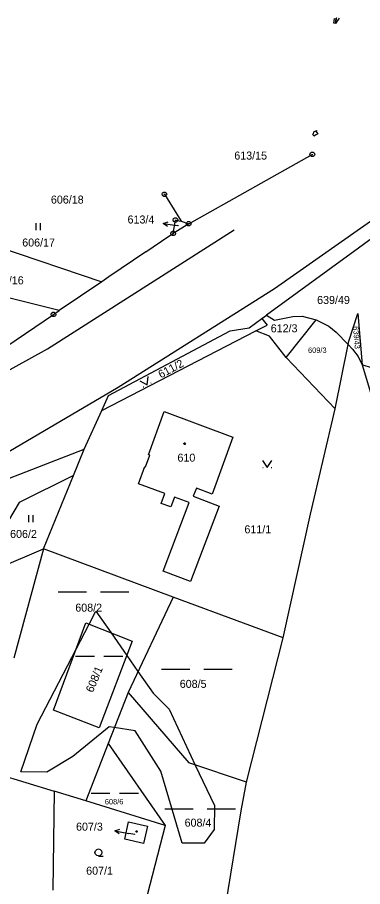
# Model space of a CAD drawing. Extents: x -759699 to -757730, y -1172308 to -1170857.
# Drawn here: x -758932.7 to -758859.4, y -1171642.4 to -1171457.7 of the extents above; entities that cross this region are included whole.
import ezdxf

# ---------------------------------------------------------------- set-up
doc = ezdxf.new("R2010")
doc.units = 0
for name, color, linetype in [('Vrstva 1', 7, 'Continuous'), ('Vrstva 11', 7, 'Continuous'), ('Vrstva 12', 7, 'Continuous'), ('Vrstva 13', 7, 'Continuous'), ('Vrstva 2', 7, 'Continuous'), ('Vrstva 3', 7, 'Continuous'), ('Vrstva 4', 7, 'Continuous'), ('Vrstva 5', 7, 'Continuous'), ('Vrstva 7', 7, 'Continuous'), ('Vrstva 8', 7, 'Continuous')]:
    doc.layers.add(name, color=color, linetype=linetype)

msp = doc.modelspace()

# ---------------------------------------------------------------- linework, layer by layer
at = {"layer": 'Vrstva 1'}
for p, q in [((-758896.35, -1171501.57), (-758870.1, -1171486.83)), ((-758870.1, -1171486.83), (-758870.1, -1171486.83)), ((-758870.1, -1171486.83), (-758870.1, -1171486.83)), ((-758901.51, -1171495.3), (-758901.51, -1171495.3)), ((-758901.51, -1171495.3), (-758898.88, -1171499.53)), ((-758901.51, -1171495.3), (-758901.51, -1171495.3)), ((-758899.66, -1171503.62), (-758899.17, -1171500.77)), ((-758899.17, -1171500.77), (-758897.96, -1171501.02)), ((-758898.88, -1171499.53), (-758897.96, -1171501.02)), ((-758896.35, -1171501.57), (-758899.66, -1171503.62)), ((-758897.96, -1171501.02), (-758896.35, -1171501.57)), ((-758896.35, -1171501.57), (-758896.35, -1171501.57)), ((-758946.27, -1171503.31), (-758914.82, -1171513.88)), ((-758905.46, -1171507.54), (-758900.57, -1171504.23)), ((-758900.57, -1171504.23), (-758899.66, -1171503.62)), ((-758856.32, -1171503.88), (-758860.31, -1171506.78)), ((-758905.46, -1171507.54), (-758913.32, -1171512.87)), ((-758905.46, -1171507.54), (-758905.46, -1171507.54)), ((-758860.31, -1171506.78), (-758879.83, -1171520.98)), ((-758923.84, -1171519.99), (-758949.6, -1171513.62)), ((-758914.82, -1171513.88), (-758923.84, -1171519.99)), ((-758913.32, -1171512.87), (-758914.82, -1171513.88)), ((-758949.81, -1171537.59), (-758925.08, -1171520.83)), ((-758925.08, -1171520.83), (-758923.84, -1171519.99)), ((-758880.8, -1171521.68), (-758879.83, -1171520.98)), ((-758879.83, -1171520.98), (-758878.12, -1171522.07)), ((-758878.12, -1171522.07), (-758874.21, -1171521.27)), ((-758874.21, -1171521.27), (-758872.25, -1171521.22)), ((-758872.25, -1171521.22), (-758869.27, -1171521.97)), ((-758862.34, -1171526.52), (-758860.47, -1171520.62)), ((-758860.47, -1171520.62), (-758859.54, -1171531.55)), ((-758883.49, -1171523.64), (-758880.8, -1171521.68)), ((-758882.07, -1171524.31), (-758879.66, -1171523.07)), ((-758880.8, -1171521.68), (-758879.66, -1171523.07)), ((-758875.67, -1171529.97), (-758869.27, -1171521.97)), ((-758869.27, -1171521.97), (-758866.62, -1171523.29)), ((-758914.83, -1171541.22), (-758882.07, -1171524.31)), ((-758913.4, -1171538.04), (-758887.56, -1171524.31)), ((-758887.56, -1171524.31), (-758883.49, -1171523.64)), ((-758879.19, -1171525.47), (-758882.07, -1171524.31)), ((-758866.62, -1171523.29), (-758865.04, -1171524.57)), ((-758865.04, -1171524.57), (-758862.49, -1171527.23)), ((-758875.67, -1171529.97), (-758879.19, -1171525.47)), ((-758862.49, -1171527.23), (-758862.34, -1171526.52)), ((-758865.27, -1171540.84), (-758862.49, -1171527.23)), ((-758862.49, -1171527.23), (-758861.55, -1171528.21)), ((-758861.55, -1171528.21), (-758860.37, -1171529.76)), ((-758865.27, -1171540.84), (-758875.67, -1171529.97)), ((-758860.37, -1171529.76), (-758859.54, -1171531.55)), ((-758859.54, -1171531.55), (-758853.32, -1171552.22)), ((-758854.03, -1171533.3), (-758859.54, -1171531.55)), ((-758914.83, -1171541.22), (-758913.4, -1171538.04)), ((-758918.53, -1171549.43), (-758914.83, -1171541.22)), ((-758904.87, -1171550.65), (-758901.54, -1171541.46)), ((-758901.54, -1171541.46), (-758886.98, -1171546.87)), ((-758870.46, -1171563.25), (-758865.27, -1171540.84)), ((-758886.98, -1171546.87), (-758891.37, -1171559.02)), ((-758937.1, -1171556.66), (-758918.53, -1171549.43)), ((-758920.82, -1171555.04), (-758918.53, -1171549.43)), ((-758905.54, -1171553.17), (-758904.64, -1171550.73)), ((-758904.64, -1171550.73), (-758904.87, -1171550.65)), ((-758907.01, -1171556.78), (-758905.69, -1171553.12)), ((-758905.69, -1171553.12), (-758905.54, -1171553.17)), ((-758920.82, -1171555.04), (-758932.37, -1171560.76)), ((-758927.21, -1171570.62), (-758920.82, -1171555.04)), ((-758901.41, -1171558.87), (-758907.01, -1171556.78)), ((-758894.72, -1171557.69), (-758895.4, -1171559.39)), ((-758891.37, -1171559.02), (-758894.72, -1171557.69)), ((-758902.17, -1171560.96), (-758901.41, -1171558.87)), ((-758899.36, -1171559.63), (-758900.14, -1171561.69)), ((-758896.27, -1171560.8), (-758899.36, -1171559.63)), ((-758895.4, -1171559.39), (-758889.92, -1171561.57)), ((-758932.37, -1171560.76), (-758942.1, -1171576.91)), ((-758900.14, -1171561.69), (-758902.17, -1171560.96)), ((-758901.8, -1171575.38), (-758896.27, -1171560.8)), ((-758889.92, -1171561.57), (-758895.98, -1171577.55)), ((-758876.28, -1171589.53), (-758870.46, -1171563.25)), ((-758942.1, -1171576.91), (-758927.21, -1171570.62)), ((-758927.21, -1171570.62), (-758933.5, -1171593.84)), ((-758899.67, -1171580.85), (-758927.21, -1171570.62)), ((-758895.98, -1171577.55), (-758901.8, -1171575.38)), ((-758899.67, -1171580.85), (-758909.22, -1171601.09)), ((-758876.28, -1171589.53), (-758899.67, -1171580.85)), ((-758925.06, -1171604.87), (-758918.21, -1171586.34)), ((-758918.21, -1171586.34), (-758908.34, -1171590.22)), ((-758884.11, -1171620.15), (-758876.28, -1171589.53)), ((-758908.34, -1171590.22), (-758915.4, -1171608.61)), ((-758909.22, -1171601.09), (-758913.47, -1171611.98)), ((-758909.22, -1171601.09), (-758896.34, -1171616.06)), ((-758915.4, -1171608.61), (-758925.06, -1171604.87)), ((-758913.47, -1171611.98), (-758918.23, -1171624.15)), ((-758913.47, -1171611.98), (-758901.34, -1171629.35)), ((-758884.11, -1171620.15), (-758896.34, -1171616.06)), ((-758939.9, -1171617.5), (-758924.94, -1171622.09)), ((-758885.19, -1171626.24), (-758884.11, -1171620.15)), ((-758924.94, -1171622.09), (-758925.22, -1171643.14)), ((-758918.23, -1171624.15), (-758924.94, -1171622.09)), ((-758901.34, -1171629.35), (-758918.23, -1171624.15)), ((-758889.72, -1171653.54), (-758885.19, -1171626.24)), ((-758909.9, -1171632.3), (-758909.14, -1171628.6)), ((-758909.14, -1171628.6), (-758905.11, -1171629.52)), ((-758905.11, -1171629.52), (-758905.95, -1171633.19)), ((-758901.34, -1171629.35), (-758905.21, -1171644.2)), ((-758905.95, -1171633.19), (-758909.9, -1171632.3))]:
    msp.add_line(p, q, dxfattribs=at)
at = {"layer": 'Vrstva 11'}
for p, q in [((-758917.52, -1171586.61), (-758916.08, -1171583.82)), ((-758916.08, -1171583.82), (-758912.85, -1171588.45)), ((-758920.27, -1171591.91), (-758917.52, -1171586.61)), ((-758912.85, -1171588.45), (-758909.5, -1171593.25)), ((-758928.54, -1171607.86), (-758920.27, -1171591.91)), ((-758909.5, -1171593.25), (-758907.13, -1171596.65)), ((-758907.13, -1171596.65), (-758903.89, -1171601.29)), ((-758903.89, -1171601.29), (-758900.52, -1171604.7)), ((-758900.52, -1171604.7), (-758894.95, -1171616.53)), ((-758932, -1171618), (-758928.54, -1171607.86)), ((-758913.27, -1171608.41), (-758920.95, -1171614.7)), ((-758912.15, -1171608.59), (-758913.27, -1171608.41)), ((-758907.76, -1171609.3), (-758912.15, -1171608.59)), ((-758902.3, -1171617.82), (-758907.76, -1171609.3)), ((-758920.95, -1171614.7), (-758926.48, -1171618.04)), ((-758894.95, -1171616.53), (-758890.9, -1171625.11)), ((-758926.48, -1171618.04), (-758932, -1171618)), ((-758897.74, -1171633.1), (-758902.3, -1171617.82)), ((-758890.9, -1171625.11), (-758890.93, -1171630.19)), ((-758890.93, -1171630.19), (-758893.07, -1171633.14)), ((-758893.07, -1171633.14), (-758897.74, -1171633.1))]:
    msp.add_line(p, q, dxfattribs=at)
at = {"layer": 'Vrstva 12'}
for p, q in [((-758904.87, -1171550.65), (-758901.54, -1171541.46)), ((-758901.54, -1171541.46), (-758886.98, -1171546.87)), ((-758886.98, -1171546.87), (-758891.37, -1171559.02)), ((-758905.54, -1171553.17), (-758904.64, -1171550.73)), ((-758904.64, -1171550.73), (-758904.87, -1171550.65)), ((-758907.01, -1171556.78), (-758905.69, -1171553.12)), ((-758905.69, -1171553.12), (-758905.54, -1171553.17)), ((-758901.41, -1171558.87), (-758907.01, -1171556.78)), ((-758894.72, -1171557.69), (-758895.4, -1171559.39)), ((-758891.37, -1171559.02), (-758894.72, -1171557.69)), ((-758902.17, -1171560.96), (-758901.41, -1171558.87)), ((-758899.36, -1171559.63), (-758900.14, -1171561.69)), ((-758896.27, -1171560.8), (-758899.36, -1171559.63)), ((-758895.4, -1171559.39), (-758889.92, -1171561.57)), ((-758900.14, -1171561.69), (-758902.17, -1171560.96)), ((-758901.8, -1171575.38), (-758896.27, -1171560.8)), ((-758889.92, -1171561.57), (-758895.98, -1171577.55)), ((-758895.98, -1171577.55), (-758901.8, -1171575.38)), ((-758909.9, -1171632.3), (-758909.14, -1171628.6)), ((-758909.14, -1171628.6), (-758905.11, -1171629.52)), ((-758905.11, -1171629.52), (-758905.95, -1171633.19)), ((-758905.95, -1171633.19), (-758909.9, -1171632.3))]:
    msp.add_line(p, q, dxfattribs=at)
at = {"layer": 'Vrstva 13'}
for p, q in [((-758865.55, -1171458.98), (-758865.41, -1171457.99)), ((-758865.41, -1171457.99), (-758865.01, -1171458.05)), ((-758864.39, -1171457.87), (-758865.16, -1171459.04)), ((-758865.01, -1171458.05), (-758865.16, -1171459.04)), ((-758865.16, -1171459.04), (-758865.01, -1171458.05)), ((-758865.01, -1171458.05), (-758864.88, -1171457.73)), ((-758864.88, -1171457.73), (-758864.88, -1171457.73)), ((-758864.39, -1171457.87), (-758864.39, -1171457.87)), ((-758865.16, -1171459.04), (-758865.55, -1171458.98)), ((-758870.02, -1171482.52), (-758869.86, -1171482.43)), ((-758869.78, -1171482.96), (-758870.02, -1171482.52)), ((-758869.86, -1171482.43), (-758869.78, -1171482.06)), ((-758869.78, -1171482.06), (-758869.21, -1171481.74)), ((-758868.9, -1171482.48), (-758869.78, -1171482.96)), ((-758869.21, -1171481.74), (-758869.3, -1171482.13)), ((-758869.3, -1171482.13), (-758869.14, -1171482.04)), ((-758869.14, -1171482.04), (-758868.9, -1171482.48))]:
    msp.add_line(p, q, dxfattribs=at)
at = {"layer": 'Vrstva 3'}
for p, q in [((-758928.85, -1171501.43), (-758928.85, -1171502.93)), ((-758927.85, -1171502.93), (-758927.85, -1171501.43)), ((-758904.404, -1171535.412), (-758904.315, -1171535.366)), ((-758906.005, -1171536.234), (-758905.916, -1171536.188)), ((-758880.62, -1171553.37), (-758880.52, -1171553.37)), ((-758878.82, -1171553.37), (-758878.72, -1171553.37)), ((-758930.4, -1171563.43), (-758930.4, -1171564.93)), ((-758929.4, -1171564.93), (-758929.4, -1171563.43)), ((-758924.09, -1171579.75), (-758918.09, -1171579.75)), ((-758915.09, -1171579.75), (-758909.09, -1171579.75)), ((-758920.385, -1171593.43), (-758916.365, -1171593.43)), ((-758914.355, -1171593.43), (-758910.335, -1171593.43)), ((-758902.14, -1171596.2), (-758896.14, -1171596.2)), ((-758893.14, -1171596.2), (-758887.14, -1171596.2)), ((-758917.095, -1171622.54), (-758913.075, -1171622.54)), ((-758911.065, -1171622.54), (-758907.045, -1171622.54)), ((-758901.43, -1171625.83), (-758895.43, -1171625.83)), ((-758892.43, -1171625.83), (-758886.43, -1171625.83))]:
    msp.add_line(p, q, dxfattribs=at)
for points in [[(-758906.734, -1171534.922), (-758905.16, -1171535.8), (-758904.955, -1171534.009)], [(-758880.67, -1171551.87), (-758879.67, -1171553.37), (-758878.67, -1171551.87)], [(-758915.52, -1171635.84), (-758915.9, -1171635.74), (-758916.17, -1171635.47), (-758916.27, -1171635.1), (-758916.17, -1171634.73), (-758915.9, -1171634.46), (-758915.53, -1171634.36), (-758915.16, -1171634.46), (-758914.89, -1171634.73), (-758914.79, -1171635.11), (-758914.89, -1171635.49), (-758915.16, -1171635.76), (-758915.54, -1171635.86), (-758914.54, -1171635.86)]]:
    msp.add_lwpolyline(points, dxfattribs=at)
at = {"layer": 'Vrstva 4'}
for p, q in [((-758878.1, -1171515.3), (-758834.46, -1171484.59)), ((-758926.31, -1171528.12), (-758886.7, -1171502.88)), ((-758886.7, -1171502.88), (-758886.7, -1171502.88)), ((-758911.34, -1171536.26), (-758878.1, -1171515.3)), ((-758948.39, -1171540.22), (-758926.31, -1171528.12)), ((-758940.14, -1171553.19), (-758911.34, -1171536.26))]:
    msp.add_line(p, q, dxfattribs=at)
at = {"layer": 'Vrstva 5'}
for points in [[(-758897.15, -1171548.12), (-758897.06, -1171548.27), (-758897.15, -1171548.42), (-758897.33, -1171548.42), (-758897.42, -1171548.27), (-758897.33, -1171548.12)], [(-758907.34, -1171630.49), (-758907.25, -1171630.64), (-758907.34, -1171630.79), (-758907.52, -1171630.79), (-758907.61, -1171630.64), (-758907.52, -1171630.49)]]:
    msp.add_lwpolyline(points, close=True, dxfattribs=at)
at = {"layer": 'Vrstva 7'}
for p, q in [((-758901.759, -1171501.507), (-758898.79, -1171501.94)), ((-758898.53, -1171501.98), (-758898.79, -1171501.94)), ((-758912.034, -1171630.472), (-758909.09, -1171631.05)), ((-758907.81, -1171631.3), (-758909.09, -1171631.05))]:
    msp.add_line(p, q, dxfattribs=at)
for points in [[(-758900.841, -1171502.146), (-758901.759, -1171501.507), (-758900.697, -1171501.157)], [(-758911.149, -1171631.155), (-758912.034, -1171630.472), (-758910.956, -1171630.174)]]:
    msp.add_lwpolyline(points, dxfattribs=at)
at = {"layer": 'Vrstva 8'}
for p, q in [((-758870.22, -1171486.83), (-758869.98, -1171486.83)), ((-758901.63, -1171495.3), (-758901.39, -1171495.3)), ((-758899.29, -1171500.77), (-758899.05, -1171500.77)), ((-758896.47, -1171501.57), (-758896.23, -1171501.57)), ((-758899.78, -1171503.62), (-758899.54, -1171503.62)), ((-758925.2, -1171520.83), (-758924.96, -1171520.83))]:
    msp.add_line(p, q, dxfattribs=at)
for points in [[(-758869.95, -1171486.35), (-758869.7, -1171486.53), (-758869.6, -1171486.82), (-758869.7, -1171487.11), (-758869.95, -1171487.29), (-758870.26, -1171487.29), (-758870.51, -1171487.11), (-758870.61, -1171486.82), (-758870.51, -1171486.53), (-758870.26, -1171486.35)], [(-758901.36, -1171494.82), (-758901.11, -1171495), (-758901.01, -1171495.29), (-758901.11, -1171495.58), (-758901.36, -1171495.76), (-758901.67, -1171495.76), (-758901.92, -1171495.58), (-758902.02, -1171495.29), (-758901.92, -1171495), (-758901.67, -1171494.82)], [(-758899.02, -1171500.29), (-758898.77, -1171500.47), (-758898.67, -1171500.76), (-758898.77, -1171501.05), (-758899.02, -1171501.23), (-758899.33, -1171501.23), (-758899.58, -1171501.05), (-758899.68, -1171500.76), (-758899.58, -1171500.47), (-758899.33, -1171500.29)], [(-758896.2, -1171501.09), (-758895.95, -1171501.27), (-758895.85, -1171501.56), (-758895.95, -1171501.85), (-758896.2, -1171502.03), (-758896.51, -1171502.03), (-758896.76, -1171501.85), (-758896.86, -1171501.56), (-758896.76, -1171501.27), (-758896.51, -1171501.09)], [(-758899.51, -1171503.14), (-758899.26, -1171503.32), (-758899.16, -1171503.61), (-758899.26, -1171503.9), (-758899.51, -1171504.08), (-758899.82, -1171504.08), (-758900.07, -1171503.9), (-758900.17, -1171503.61), (-758900.07, -1171503.32), (-758899.82, -1171503.14)], [(-758924.93, -1171520.35), (-758924.68, -1171520.53), (-758924.58, -1171520.82), (-758924.68, -1171521.11), (-758924.93, -1171521.29), (-758925.24, -1171521.29), (-758925.49, -1171521.11), (-758925.59, -1171520.82), (-758925.49, -1171520.53), (-758925.24, -1171520.35)]]:
    msp.add_lwpolyline(points, close=True, dxfattribs=at)

# ---------------------------------------------------------------- texts
at = {"layer": 'Vrstva 2'}
for s, height, p in [('613/15', 1.7, (-758886.67, -1171487.93)), ('606/18', 1.7, (-758925.621, -1171497.28)), ('613/4', 0.1, (-758898.717, -1171501.98)), ('606/17', 1.7, (-758931.711, -1171506.4)), ('606/16', 1.7, (-758938.351, -1171514.43)), ('639/49', 1.7, (-758869.079, -1171518.6)), ('612/3', 1.7, (-758878.936, -1171524.62)), ('609/3', 1.14, (-758871.009, -1171528.99)), ('610', 1.7, (-758898.743, -1171552.1)), ('611/1', 1.7, (-758884.519, -1171567.32)), ('606/2', 1.7, (-758934.284, -1171568.3)), ('608/2', 1.7, (-758920.44, -1171583.95)), ('608/5', 1.7, (-758898.254, -1171600.14)), ('608/6', 1.14, (-758914.168, -1171624.88)), ('608/4', 1.7, (-758897.227, -1171629.62)), ('607/3', 0.1, (-758908.016, -1171631.3)), ('607/1', 1.7, (-758918.132, -1171639.82))]:
    msp.add_text(s, height=height, dxfattribs=at).set_placement(p)
for s, height, rotation, p in [('639/43', 1.14, 274.56138, (-758861.459, -1171523.378)), ('611/2', 1.7, 28.24682, (-758902.256, -1171534.45)), ('608/1', 1.7, 67.55173, (-758916.718, -1171601.261))]:
    msp.add_text(s, height=height, rotation=rotation, dxfattribs=at).set_placement(p)
at = {"layer": 'Vrstva 7'}
for s, p in [('613/4', (-758909.342, -1171501.51)), ('607/3', (-758920.282, -1171630.47))]:
    msp.add_text(s, height=1.7, dxfattribs=at).set_placement(p)

doc.saveas('drawing.dxf')
